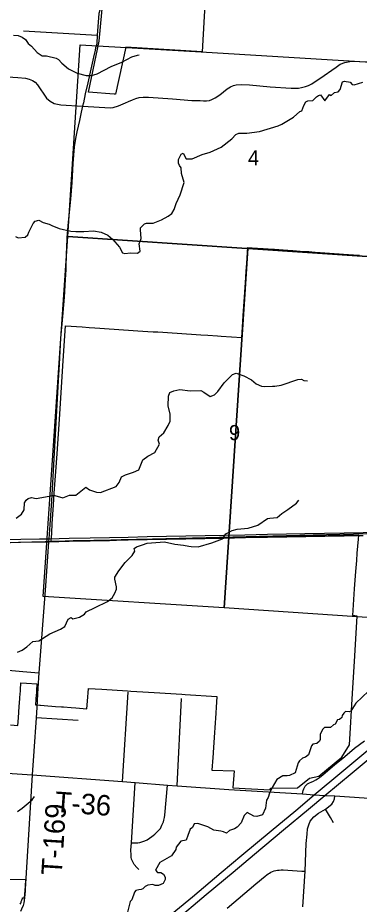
# Model space of a CAD drawing. Extents: x 0 to 34, y 0 to 26.1.
# Drawn here: x 25.753 to 26.701, y 18.306 to 20.765 of the extents above; entities that cross this region are included whole.
import ezdxf

# ---------------------------------------------------------------- set-up
doc = ezdxf.new("R2010")
doc.units = 0
for name, color, linetype in [('GM_X_City_Street', 7, 'Continuous'), ('GM_X_Interstate_Route', 7, 'Continuous'), ('GM_X_Minor_River', 7, 'Continuous'), ('GM_X_Rail_Line', 7, 'Continuous'), ('GM_X_Section', 7, 'Continuous'), ('GM_X_Section_Text', 7, 'Continuous'), ('GM_X_Township_Road', 7, 'Continuous'), ('GM_X_Township_Road_Text', 7, 'Continuous'), ('GM_X_US_Route', 7, 'Continuous'), ('SC_Scratch1', 7, 'Continuous')]:
    doc.layers.add(name, color=color, linetype=linetype)

msp = doc.modelspace()

# ---------------------------------------------------------------- linework, layer by layer
at = {"layer": 'GM_X_City_Street'}
msp.add_line((25.7694, 20.7294), (25.9738, 20.7169), dxfattribs=at)
for points in [[(25.9331, 20.5199), (26.0108, 20.5155), (26.0178, 20.5159), (26.0331, 20.5207), (26.0523, 20.5295), (26.0609, 20.5334), (26.0713, 20.5375), (26.0812, 20.5416), (26.0903, 20.5441), (26.101, 20.5453), (26.1163, 20.5449), (26.1824, 20.5408), (26.2366, 20.5362), (26.2593, 20.5354), (26.2684, 20.535), (26.2771, 20.535), (26.285, 20.5358), (26.292, 20.5383), (26.3011, 20.5433), (26.3143, 20.5515), (26.3346, 20.5677), (26.3436, 20.5739), (26.3515, 20.5776), (26.3589, 20.5796), (26.3738, 20.5805), (26.3961, 20.5792), (26.454, 20.5739), (26.5119, 20.5697), (26.524, 20.5697), (26.5326, 20.5704), (26.5407, 20.5717), (26.5512, 20.5747), (26.56, 20.5777), (26.5689, 20.5817), (26.6032, 20.6051), (26.6246, 20.6201), (26.6366, 20.6286), (26.6482, 20.6361), (26.6604, 20.6408), (26.6746, 20.6442), (26.6823, 20.6445), (26.8002, 20.6395)], [(25.4164, 20.5895), (25.4287, 20.6036), (25.4376, 20.6094), (25.4436, 20.6134), (25.4579, 20.6176), (25.4671, 20.6187), (25.5972, 20.6096), (25.7534, 20.5998), (25.7744, 20.5977), (25.7847, 20.5948), (25.7945, 20.5911), (25.8012, 20.5863), (25.8082, 20.5794), (25.8332, 20.5418), (25.8433, 20.5339), (25.8543, 20.5276), (25.8728, 20.5234), (25.9331, 20.5199)], [(25.5839, 18.9633), (25.5874, 18.9652), (25.5911, 18.9663), (25.5934, 18.9667), (25.5972, 18.9667), (25.6055, 18.9662), (25.6532, 18.9615), (25.6831, 18.9587), (25.6838, 18.9587), (25.7266, 18.9554), (25.767, 18.9518), (25.812, 18.948)]]:
    msp.add_lwpolyline(points, dxfattribs=at)
at = {"layer": 'GM_X_Interstate_Route'}
for points in [[(26.1558, 18.26), (26.2377, 18.3275), (26.3172, 18.3941), (26.3753, 18.4423), (26.4566, 18.5098), (26.5247, 18.5668), (26.5759, 18.6102), (26.6523, 18.6739), (26.7577, 18.7617)], [(26.186, 18.2581), (26.2756, 18.3333), (26.3509, 18.3957), (26.4101, 18.445), (26.4907, 18.5127), (26.5597, 18.5703), (26.6049, 18.6077), (26.6813, 18.6713), (26.7867, 18.7592)]]:
    msp.add_lwpolyline(points, dxfattribs=at)
at = {"layer": 'GM_X_Minor_River'}
for points in [[(25.7412, 20.7172), (25.7548, 20.7156), (25.7654, 20.7118), (25.7748, 20.705), (25.7824, 20.6943), (25.7915, 20.6867), (25.8073, 20.6693), (25.8206, 20.6598), (25.8334, 20.6598), (25.8599, 20.6533), (25.8659, 20.6491), (25.8754, 20.6392), (25.8939, 20.624), (25.9177, 20.6118), (25.9434, 20.605), (25.9578, 20.605), (25.9737, 20.6099), (26.012, 20.6299), (26.0419, 20.642), (26.0695, 20.6568), (26.0854, 20.6613), (26.0903, 20.6625)], [(26.5578, 20.5348), (26.5718, 20.5355), (26.5824, 20.5458), (26.5873, 20.5499), (26.5933, 20.5511), (26.6054, 20.5351), (26.6183, 20.5526), (26.6232, 20.5499), (26.6319, 20.5582), (26.6425, 20.5601), (26.6482, 20.5666), (26.6543, 20.5874), (26.6596, 20.5893), (26.6649, 20.5886), (26.6709, 20.5874), (26.6759, 20.587), (26.6815, 20.5802), (26.6868, 20.579), (26.7107, 20.5862)], [(25.7473, 20.1586), (25.7548, 20.1552), (25.7738, 20.1567), (25.7817, 20.1635), (25.7836, 20.1707), (25.7961, 20.1942), (25.8014, 20.2014), (25.8117, 20.204), (25.8238, 20.1976), (25.8404, 20.1923), (25.8483, 20.1892), (25.8684, 20.1805), (25.9005, 20.1732), (25.9141, 20.1721), (25.9365, 20.1728), (25.9637, 20.1739), (25.9849, 20.1704), (26.003, 20.1625), (26.0166, 20.1514), (26.0355, 20.1294), (26.0435, 20.1131), (26.0506, 20.1116), (26.0658, 20.1134), (26.0855, 20.1119), (26.0926, 20.118), (26.0904, 20.1384), (26.0961, 20.1529), (26.0935, 20.1775), (26.0939, 20.1825), (26.1049, 20.1935), (26.1101, 20.1953), (26.1287, 20.1957), (26.1525, 20.2048), (26.1707, 20.215), (26.1806, 20.2226), (26.1874, 20.2336), (26.1931, 20.2503), (26.2041, 20.2742), (26.2147, 20.3087), (26.2072, 20.3334), (26.2064, 20.3493), (26.2023, 20.3554), (26.1993, 20.3618), (26.1997, 20.3724), (26.2065, 20.3872), (26.2118, 20.3895), (26.2208, 20.3743), (26.2375, 20.3739), (26.2647, 20.3856), (26.2867, 20.3921), (26.3174, 20.4065), (26.3469, 20.4292), (26.3583, 20.4417), (26.3666, 20.4455), (26.3779, 20.4447), (26.3889, 20.4455), (26.4237, 20.45), (26.4756, 20.4658), (26.4862, 20.4704), (26.4998, 20.4787), (26.518, 20.4897), (26.5362, 20.5056), (26.5418, 20.5071), (26.5468, 20.5215), (26.5528, 20.5318), (26.5578, 20.5348)], [(25.7486, 19.3769), (25.7633, 19.3886), (25.7713, 19.4008), (25.7717, 19.4201), (25.7762, 19.4269), (25.7819, 19.4315), (25.7918, 19.4345), (25.8046, 19.4322), (25.8508, 19.4401), (25.8565, 19.4405), (25.8784, 19.4336), (25.8966, 19.4408), (25.914, 19.4412), (25.9424, 19.4632), (25.9522, 19.4556), (25.9722, 19.4491), (25.9825, 19.4487), (26.026, 19.4653), (26.0351, 19.4767), (26.0415, 19.4919), (26.0521, 19.4979), (26.0748, 19.5048), (26.0896, 19.5112), (26.1006, 19.5389), (26.1142, 19.5491), (26.1336, 19.5593), (26.1464, 19.5828), (26.1427, 19.5938), (26.1453, 19.6033), (26.1586, 19.6139), (26.1707, 19.634), (26.1757, 19.6466), (26.1757, 19.6655), (26.1708, 19.6887), (26.1712, 19.716), (26.1754, 19.7255), (26.1867, 19.7308), (26.2034, 19.7338), (26.2321, 19.7307), (26.2613, 19.7311), (26.2696, 19.7265), (26.287, 19.7151), (26.2987, 19.7193), (26.3086, 19.7284), (26.3264, 19.753), (26.3495, 19.7754), (26.3589, 19.7799), (26.365, 19.7776), (26.3809, 19.7723), (26.402, 19.7613), (26.4149, 19.7502), (26.43, 19.7434), (26.4391, 19.7422), (26.4599, 19.7437), (26.4667, 19.7437), (26.4845, 19.746), (26.5303, 19.7623), (26.5409, 19.7626), (26.5473, 19.7596), (26.5575, 19.7584)], [(25.7522, 19.0057), (25.7655, 19.011), (25.7787, 19.0201), (25.7947, 19.0356), (25.8117, 19.0375), (25.8424, 19.0568), (25.8723, 19.069), (25.8836, 19.0769), (25.8935, 19.0974), (25.9011, 19.1016), (25.906, 19.0981), (25.9245, 19.1027), (25.9385, 19.1114), (25.9431, 19.1174), (25.9684, 19.1292), (26.0025, 19.1466), (26.015, 19.1564), (26.023, 19.1697), (26.0275, 19.1807), (26.0275, 19.1868), (26.0223, 19.2077), (26.023, 19.2134), (26.034, 19.2316), (26.0511, 19.2543), (26.0708, 19.2736), (26.0783, 19.2858), (26.0761, 19.293), (26.0829, 19.2975), (26.0996, 19.3032), (26.1128, 19.3078), (26.1601, 19.3119), (26.1888, 19.305), (26.2127, 19.3027), (26.2278, 19.2996), (26.2342, 19.2989), (26.2535, 19.2981), (26.2918, 19.3091), (26.3209, 19.3204), (26.3304, 19.3337), (26.3482, 19.3431), (26.3625, 19.3469), (26.3928, 19.3495), (26.4193, 19.3579), (26.4462, 19.376), (26.4523, 19.3776), (26.4734, 19.3794), (26.4856, 19.39), (26.503, 19.401), (26.5265, 19.4188), (26.5329, 19.4272)], [(26.7267, 18.8971), (26.6911, 18.8642), (26.6774, 18.8418), (26.6725, 18.8399), (26.6627, 18.8407), (26.6577, 18.8369), (26.6536, 18.8297), (26.6521, 18.8244), (26.646, 18.8191), (26.6407, 18.8179), (26.6342, 18.8062), (26.6289, 18.8039), (26.621, 18.7963), (26.6043, 18.7967), (26.5994, 18.7925), (26.5922, 18.7785), (26.5926, 18.7637), (26.5903, 18.7584), (26.5827, 18.7527), (26.5718, 18.7504), (26.568, 18.7455), (26.56, 18.7205), (26.5517, 18.7144), (26.5437, 18.7121), (26.5346, 18.7038), (26.5312, 18.6985), (26.5228, 18.6708), (26.5069, 18.664), (26.5005, 18.6629), (26.4884, 18.6629), (26.4725, 18.6523), (26.4589, 18.6303), (26.4513, 18.6143), (26.4478, 18.6022), (26.4437, 18.5954), (26.4402, 18.5726), (26.4323, 18.5548), (26.4168, 18.5502), (26.4084, 18.5506), (26.3899, 18.5605), (26.3812, 18.5529), (26.3732, 18.5324), (26.3622, 18.5203), (26.3547, 18.5158), (26.341, 18.5108), (26.3323, 18.5036), (26.3244, 18.5074), (26.3168, 18.509), (26.2975, 18.512), (26.2805, 18.5208), (26.2533, 18.5303), (26.2423, 18.5292), (26.2381, 18.5197), (26.2317, 18.5151), (26.2249, 18.4973), (26.2207, 18.4844), (26.2059, 18.4818), (26.1927, 18.4647), (26.1915, 18.4579), (26.1794, 18.4412), (26.1472, 18.4226), (26.1355, 18.4006), (26.1411, 18.3942), (26.1498, 18.3941), (26.1574, 18.3903), (26.1623, 18.382), (26.1619, 18.3748), (26.157, 18.3642), (26.1437, 18.3589), (26.135, 18.3581), (26.1282, 18.3608), (26.1142, 18.3593), (26.107, 18.3559), (26.1006, 18.349), (26.0953, 18.3471), (26.0896, 18.3464), (26.0809, 18.3445), (26.0775, 18.3396), (26.0695, 18.3187), (26.0654, 18.3138), (26.0581, 18.2842)], [(25.7524, 18.5639), (25.7657, 18.5726), (25.7937, 18.5965), (25.8002, 18.6056)]]:
    msp.add_lwpolyline(points, dxfattribs=at)
at = {"layer": 'GM_X_Rail_Line'}
msp.add_lwpolyline([(25.3226, 19.2999), (25.5312, 19.3051), (26.9819, 19.3408), (27.9322, 19.3586), (28.1615, 19.3637)], dxfattribs=at)
at = {"layer": 'GM_X_Section'}
for points in [[(25.926, 20.6906), (26.2619, 20.6708), (26.7939, 20.6382), (26.9267, 20.63), (26.8884, 20.0918), (26.3915, 20.1255), (26.3885, 20.1257), (25.892, 20.1588)], [(25.892, 20.1588), (26.3885, 20.1257), (26.3915, 20.1255), (26.3256, 19.1287), (25.8234, 19.1601)], [(26.3915, 20.1255), (26.8884, 20.0918), (26.8184, 19.0949), (26.3256, 19.1287)]]:
    msp.add_lwpolyline(points, close=True, dxfattribs=at)
at = {"layer": 'GM_X_Township_Road'}
for p, q in [((25.8081, 18.8905), (25.8058, 18.852)), ((26.0437, 18.6467), (26.0598, 18.8945)), ((26.1959, 18.6353), (26.2074, 18.8772)), ((25.9209, 18.8158), (25.804, 18.8231)), ((25.7738, 18.3439), (25.7723, 18.3239))]:
    msp.add_line(p, q, dxfattribs=at)
for points in [[(25.9906, 20.9), (25.9835, 20.8326), (25.9806, 20.786), (25.9786, 20.7773), (25.9738, 20.7169), (25.9737, 20.7154), (25.9723, 20.6961), (25.9717, 20.6896), (25.9709, 20.6869)], [(25.9709, 20.6869), (25.9694, 20.6815), (25.9682, 20.6757), (25.9631, 20.656), (25.9598, 20.6389), (25.9558, 20.6223), (25.9474, 20.5848), (25.9402, 20.5545), (25.9354, 20.5292), (25.9331, 20.5199), (25.929, 20.5031), (25.9245, 20.4807), (25.9173, 20.4485), (25.9136, 20.43), (25.9096, 20.4073), (25.9063, 20.361), (25.9034, 20.3083), (25.8998, 20.2624), (25.8929, 20.1983), (25.8897, 20.1562), (25.8882, 20.1255)], [(25.8882, 20.1255), (25.8881, 20.1236), (25.8877, 20.1156), (25.8871, 20.0674), (25.8852, 20.039), (25.8823, 19.99), (25.8774, 19.9366), (25.8721, 19.877), (25.8678, 19.8042), (25.8658, 19.7596), (25.851, 19.4916), (25.8467, 19.4252), (25.8424, 19.3592), (25.8397, 19.3204), (25.8388, 19.3121)], [(25.8388, 19.3121), (25.8306, 19.19), (25.812, 18.948), (25.809, 18.9059), (25.8081, 18.8905)], [(25.8058, 18.852), (25.804, 18.8231), (25.798, 18.7309), (25.7935, 18.6656)], [(26.5433, 18.613), (26.5453, 18.6217), (26.5467, 18.6263), (26.5505, 18.6344), (26.5573, 18.6403), (26.5626, 18.6429), (26.5676, 18.6455), (26.574, 18.6481), (26.5801, 18.6518), (26.5851, 18.6544), (26.5908, 18.6581), (26.6008, 18.6659), (26.6317, 18.6933), (26.6604, 18.7164), (26.6879, 18.7392), (26.7151, 18.7598)], [(25.5797, 18.6805), (25.6679, 18.6737), (25.7935, 18.6656)], [(25.7935, 18.6656), (25.7741, 18.3479), (25.7738, 18.3439)], [(25.7935, 18.6656), (26.0437, 18.6467), (26.0794, 18.644), (26.1683, 18.637), (26.1959, 18.6353), (26.3393, 18.6245), (26.5433, 18.613), (26.5759, 18.6102), (26.6049, 18.6077), (26.6331, 18.6069), (26.9312, 18.5865), (27.5853, 18.5352), (27.752, 18.5234), (28.012, 18.5079)], [(26.0893, 18.4026), (26.0833, 18.408), (26.0766, 18.4168), (26.074, 18.4206), (26.0707, 18.4275), (26.0692, 18.4313), (26.0681, 18.4374), (26.0675, 18.4435), (26.0673, 18.4568), (26.069, 18.4765), (26.0794, 18.644)], [(26.069, 18.4765), (26.0861, 18.4767), (26.0921, 18.4781), (26.1062, 18.4821), (26.1123, 18.4847), (26.1191, 18.4896), (26.1256, 18.4944), (26.1294, 18.4974), (26.1333, 18.5011), (26.1371, 18.5045), (26.1413, 18.5086), (26.1452, 18.5131), (26.1494, 18.5169), (26.1513, 18.521), (26.1533, 18.5256), (26.1548, 18.5297), (26.1572, 18.5354), (26.1584, 18.5399), (26.1604, 18.5471), (26.1616, 18.5532), (26.1683, 18.637)], [(26.5444, 18.2994), (26.5509, 18.3978), (26.5536, 18.4753), (26.5559, 18.5011), (26.5572, 18.5158), (26.5609, 18.5268), (26.5649, 18.5368), (26.5748, 18.5488), (26.588, 18.559), (26.6067, 18.5698), (26.6249, 18.5839), (26.6293, 18.5912), (26.6323, 18.5984), (26.6331, 18.6069)], [(26.6291, 18.5325), (26.6211, 18.5472), (26.6067, 18.5698)], [(26.3342, 18.2958), (26.4138, 18.3627), (26.44, 18.3848), (26.4439, 18.3878), (26.4477, 18.3906), (26.4517, 18.3931), (26.4556, 18.3952), (26.4602, 18.3972), (26.4645, 18.3987), (26.4692, 18.3999), (26.4735, 18.4008), (26.4782, 18.4014), (26.4837, 18.4016), (26.4898, 18.4015), (26.5418, 18.3983), (26.5509, 18.3978)], [(25.7723, 18.3239), (25.7706, 18.3108), (25.768, 18.3027), (25.7641, 18.2927), (25.7612, 18.2862)]]:
    msp.add_lwpolyline(points, dxfattribs=at)
at = {"layer": 'GM_X_US_Route'}
msp.add_line((26.6838, 19.3291), (26.6958, 19.3293), dxfattribs=at)
for points in [[(25.8397, 19.3204), (25.8684, 19.3209), (25.8962, 19.3215), (25.9541, 19.3228), (26.0074, 19.3239), (26.0593, 19.325), (26.1127, 19.3261), (26.1662, 19.327), (26.2193, 19.3282), (26.2732, 19.329), (26.3251, 19.3302), (26.3834, 19.3311), (26.4462, 19.3325), (26.4993, 19.3335), (26.55, 19.3344), (26.6045, 19.3355), (26.6587, 19.3367), (26.7118, 19.3377), (26.765, 19.3389), (26.7831, 19.3392)], [(26.0274, 19.3162), (26.0594, 19.3169), (26.1128, 19.318), (26.1663, 19.3189), (26.2193, 19.3201), (26.2725, 19.3213), (26.3251, 19.3221), (26.3854, 19.3233), (26.4463, 19.3244), (26.4994, 19.3254), (26.553, 19.3267), (26.6056, 19.3277), (26.6588, 19.3286), (26.6838, 19.3291)], [(26.6958, 19.3293), (26.7118, 19.3296)], [(25.6731, 19.3088), (25.7051, 19.3093), (25.7609, 19.3106), (25.8124, 19.3117), (25.8388, 19.3121)], [(25.6733, 19.3172), (25.7059, 19.3177), (25.7617, 19.3189), (25.8132, 19.32), (25.8397, 19.3204)], [(25.8388, 19.3121), (25.8962, 19.3134), (25.9542, 19.3147), (26.0074, 19.3158), (26.0274, 19.3162)]]:
    msp.add_lwpolyline(points, dxfattribs=at)
at = {"layer": 'SC_Scratch1'}
for points in [[(26.2777, 20.9), (26.2646, 20.6708), (26.0532, 20.6836), (26.0244, 20.5534), (26.0211, 20.5536), (25.9492, 20.5585), (25.9795, 20.7), (25.9976, 20.9)], [(25.7333, 18.8038), (25.7539, 18.8024), (25.7553, 18.8236), (25.7574, 18.8547), (25.759, 18.8766), (25.7592, 18.8797), (25.7606, 18.8982), (25.7608, 18.9012), (25.7622, 18.9206), (25.7777, 18.9195), (25.8066, 18.9174), (25.8054, 18.898), (25.8052, 18.895), (25.8045, 18.8856), (25.8033, 18.8771), (25.8031, 18.874), (25.8021, 18.8599), (25.815, 18.8587), (25.816, 18.8586), (25.8364, 18.857), (25.8475, 18.8562), (25.8584, 18.8553), (25.8749, 18.854), (25.8801, 18.8536), (25.9018, 18.8519), (25.9144, 18.8509), (25.9452, 18.8486), (25.9468, 18.8698), (25.9496, 18.9052), (25.987, 18.903), (26.0579, 18.8985), (26.0667, 18.8979), (26.1001, 18.8958), (26.1316, 18.8938), (26.2086, 18.8889), (26.2181, 18.8883), (26.306, 18.8827), (26.3049, 18.8669), (26.304, 18.8532), (26.3028, 18.8365), (26.3019, 18.8228), (26.301, 18.8098), (26.3001, 18.7961), (26.2991, 18.7824), (26.2982, 18.7687), (26.2973, 18.755), (26.2963, 18.7413), (26.2954, 18.7276), (26.2952, 18.7252), (26.2945, 18.7139), (26.292, 18.6784), (26.3541, 18.6768), (26.35, 18.6298), (26.454, 18.6234), (26.4543, 18.6283), (26.5296, 18.6297), (26.5624, 18.6566), (26.589, 18.6616), (26.652, 18.7147), (26.6734, 18.7488), (26.6818, 18.8907), (26.6881, 18.9953), (26.6947, 19.1059), (26.6832, 19.1069), (26.6877, 19.1816), (26.6914, 19.2294), (26.6938, 19.2599), (26.6954, 19.2807), (26.6983, 19.3187), (26.6993, 19.3301), (26.4008, 19.3241), (26.3361, 19.3228), (26.3052, 19.3221), (26.2491, 19.321), (26.1921, 19.3199), (26.1599, 19.3192), (26.1544, 19.3191), (26.1165, 19.3183), (26.0908, 19.3178), (26.083, 19.3177), (26.0539, 19.3171), (26.0406, 19.3168), (25.9817, 19.3156), (25.9712, 19.3154), (25.9647, 19.3153), (25.9456, 19.3149), (25.9267, 19.3145), (25.9068, 19.3141), (25.885, 19.3136), (25.8464, 19.3129), (25.8477, 19.3361), (25.8492, 19.3624), (25.8521, 19.4131), (25.8547, 19.4471), (25.8591, 19.5071), (25.8627, 19.556), (25.8696, 19.6655), (25.8771, 19.7853), (25.8791, 19.8137), (25.8859, 19.9109), (25.932, 19.9076), (25.9514, 19.9062), (25.9676, 19.905), (25.9807, 19.9042), (25.9939, 19.9033), (26.0071, 19.9025), (26.0204, 19.9016), (26.0336, 19.9007), (26.047, 19.8999), (26.0601, 19.899), (26.0733, 19.8982), (26.0864, 19.8973), (26.1002, 19.8964), (26.1146, 19.8955), (26.1287, 19.8945), (26.1423, 19.8937), (26.1555, 19.8928), (26.1685, 19.8919), (26.1817, 19.8911), (26.1952, 19.8902), (26.2085, 19.8893), (26.2217, 19.8885), (26.2351, 19.8876), (26.2483, 19.8867), (26.2615, 19.8859), (26.281, 19.8847), (26.3072, 19.8828), (26.3172, 19.8821), (26.3747, 19.878), (26.3775, 19.9232), (26.3785, 19.9382), (26.3795, 19.952), (26.3804, 19.9645), (26.3813, 19.9781), (26.3822, 19.9911), (26.3831, 20.0044), (26.384, 20.0179), (26.3849, 20.0309), (26.3859, 20.0445), (26.3871, 20.0622), (26.3886, 20.0847), (26.3896, 20.099), (26.3916, 20.1282), (26.4036, 20.1274), (26.4345, 20.1253), (26.448, 20.1244), (26.4652, 20.1232), (26.4894, 20.1214), (26.5165, 20.1197), (26.5365, 20.1182), (26.5606, 20.1165), (26.5786, 20.1152), (26.5919, 20.1143), (26.6051, 20.1134), (26.6183, 20.1124), (26.6316, 20.1115), (26.645, 20.1105), (26.6575, 20.1096), (26.6706, 20.1087), (26.6845, 20.1077), (26.701, 20.1065)], [(25.7603, 18.3063), (25.7614, 18.3093), (25.7624, 18.312), (25.7632, 18.3139), (25.7639, 18.3159), (25.7645, 18.3179), (25.7653, 18.3202), (25.7661, 18.3226), (25.7667, 18.3246), (25.7721, 18.3245), (25.7746, 18.3561), (25.7758, 18.375), (25.6576, 18.3732)]]:
    msp.add_lwpolyline(points, dxfattribs=at)

# ---------------------------------------------------------------- texts
at = {"layer": 'GM_X_Section_Text'}
for s, p in [('4', (26.3917, 20.3557)), ('9', (26.3392, 19.5937))]:
    msp.add_text(s, height=0.0419, rotation=0, dxfattribs=at).set_placement(p)
at = {"layer": 'GM_X_Township_Road_Text'}
for s, rotation, p in [('T-36', 355.7645, (25.8544, 18.5628)), ('T-169', 86.3536, (25.8751, 18.3857))]:
    msp.add_text(s, height=0.05682, rotation=rotation, dxfattribs=at).set_placement(p)

doc.saveas('drawing.dxf')
